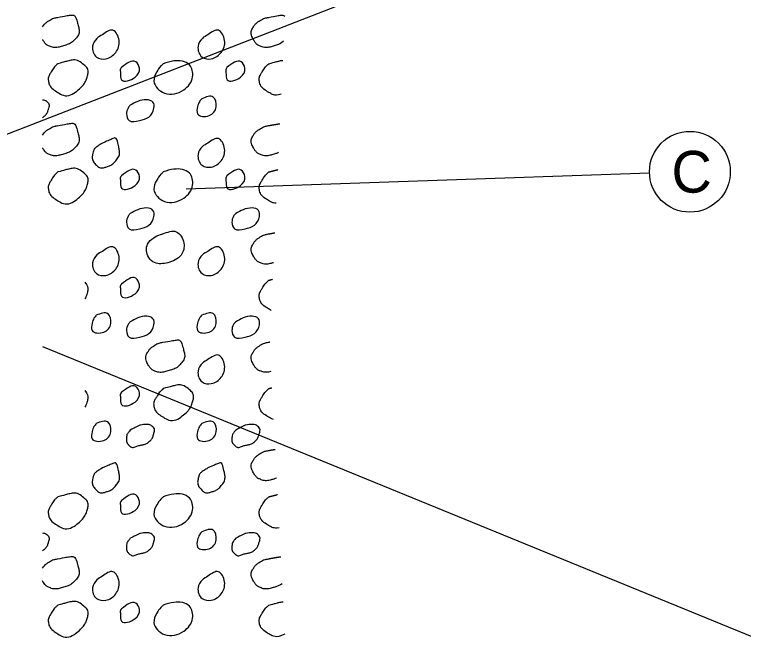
# Model space of a CAD drawing. Extents: x -1270 to 3371, y -118 to 220.
# Drawn here: x 148.55 to 172.98, y 141.14 to 162.09 of the extents above; entities that cross this region are included whole.
import ezdxf

# ---------------------------------------------------------------- set-up
doc = ezdxf.new("R2010")
doc.units = 0
for name, color, linetype in [('GE_P_Alignment', 7, 'Continuous'), ('GE_P_Alignment_100_Bearings', 7, 'Continuous'), ('TX_P_1', 7, 'Continuous')]:
    doc.layers.add(name, color=color, linetype=linetype)

msp = doc.modelspace()

# ---------------------------------------------------------------- linework, layer by layer
at = {"layer": 'GE_P_Alignment'}
msp.add_line((169.835, 156.773), (154.299, 156.237), dxfattribs=at)
at = {"layer": 'GE_P_Alignment_100_Bearings'}
for points, degree in [([(149.976, 161.994), (150.127, 162.02), (150.279, 162.049), (150.43, 162.07), (150.581, 162.091), (150.652, 161.832), (150.689, 161.69), (150.724, 161.561), (150.702, 161.403), (150.593, 161.283), (150.46, 161.136), (150.311, 161.079), (150.147, 161.031), (150.006, 160.989), (149.848, 160.974), (149.707, 161.033), (149.622, 161.069), (149.56, 161.131), (149.508, 161.211), (149.499, 161.225), (149.491, 161.239), (149.483, 161.254)], 3), ([(157.048, 161.994), (157.199, 162.02), (157.351, 162.049), (157.502, 162.07), (157.543, 162.075), (157.577, 162.061), (157.607, 162.034)], 3), ([(149.483, 161.676), (149.532, 161.752), (149.596, 161.819), (149.676, 161.87), (149.75, 161.917), (149.82, 161.961), (149.902, 161.978), (149.929, 161.984), (149.957, 161.99), (149.984, 161.996)], 3), ([(157.568, 161.193), (157.461, 161.109), (157.344, 161.068), (157.219, 161.031), (157.077, 160.989), (156.919, 160.974), (156.779, 161.033), (156.693, 161.069), (156.631, 161.131), (156.579, 161.211), (156.493, 161.345), (156.467, 161.53), (156.543, 161.656), (156.593, 161.74), (156.661, 161.814), (156.748, 161.87), (156.821, 161.917), (156.892, 161.961), (156.974, 161.978), (157.001, 161.984), (157.029, 161.99), (157.056, 161.996)], 3), ([(149.997, 160.442), (150.115, 160.474), (150.234, 160.505), (150.353, 160.536), (150.526, 160.58), (150.7, 160.549), (150.874, 160.404), (151.008, 160.292), (151.017, 160.125), (150.981, 160.001), (150.936, 159.845), (150.837, 159.696), (150.685, 159.566), (150.495, 159.404), (150.231, 159.34), (150.037, 159.456), (149.879, 159.549), (149.713, 159.689), (149.683, 159.854), (149.664, 159.957), (149.717, 160.076), (149.778, 160.172), (149.821, 160.241), (149.859, 160.31), (149.916, 160.365), (149.943, 160.391), (149.97, 160.417), (149.997, 160.442)], 3), ([(157.069, 160.442), (157.187, 160.474), (157.306, 160.505), (157.424, 160.536), (157.462, 160.545), (157.5, 160.552), (157.538, 160.554)], 3), ([(157.486, 159.419), (157.355, 159.382), (157.22, 159.389), (157.109, 159.456), (156.951, 159.549), (156.785, 159.689), (156.754, 159.854), (156.735, 159.957), (156.789, 160.076), (156.849, 160.172), (156.893, 160.241), (156.931, 160.31), (156.988, 160.365), (157.015, 160.391), (157.042, 160.417), (157.069, 160.442)], 3), ([(149.483, 159.234), (149.542, 159.229), (149.598, 159.207), (149.651, 159.154), (149.712, 159.094), (149.703, 159.014), (149.685, 158.951), (149.656, 158.846), (149.617, 158.739), (149.514, 158.654), (149.504, 158.646), (149.494, 158.638), (149.483, 158.631)], 3), ([(149.976, 158.363), (150.127, 158.389), (150.279, 158.418), (150.43, 158.439), (150.581, 158.46), (150.652, 158.201), (150.689, 158.059), (150.724, 157.93), (150.702, 157.773), (150.593, 157.653), (150.46, 157.505), (150.311, 157.448), (150.147, 157.4), (150.006, 157.359), (149.848, 157.343), (149.707, 157.403), (149.622, 157.439), (149.56, 157.501), (149.508, 157.581), (149.499, 157.595), (149.491, 157.609), (149.483, 157.623)], 3), ([(149.483, 158.046), (149.532, 158.121), (149.596, 158.188), (149.676, 158.239), (149.75, 158.286), (149.82, 158.33), (149.902, 158.348), (149.929, 158.353), (149.957, 158.359), (149.984, 158.365)], 3), ([(157.395, 157.462), (157.338, 157.437), (157.28, 157.418), (157.219, 157.4), (157.077, 157.359), (156.919, 157.343), (156.779, 157.403), (156.693, 157.439), (156.631, 157.501), (156.579, 157.581), (156.493, 157.715), (156.467, 157.899), (156.543, 158.026), (156.593, 158.11), (156.661, 158.184), (156.748, 158.239), (156.821, 158.286), (156.892, 158.33), (156.974, 158.348), (157.001, 158.353), (157.029, 158.359), (157.056, 158.365)], 3), ([(157.048, 158.363), (157.178, 158.386), (157.309, 158.41), (157.44, 158.43)], 2), ([(151.492, 157.781), (151.609, 157.831), (151.726, 157.881), (151.844, 157.932), (151.965, 157.984), (152.024, 157.717), (152.051, 157.593), (152.079, 157.462), (152.045, 157.315), (151.939, 157.188), (151.84, 157.069), (151.726, 157.012), (151.606, 156.976), (151.51, 156.947), (151.389, 156.942), (151.295, 157.035), (151.182, 157.148), (151.139, 157.28), (151.162, 157.394), (151.18, 157.485), (151.223, 157.605), (151.308, 157.662), (151.369, 157.703), (151.431, 157.741), (151.492, 157.781)], 3), ([(149.997, 156.812), (150.115, 156.843), (150.234, 156.874), (150.353, 156.905), (150.526, 156.95), (150.7, 156.918), (150.874, 156.773), (151.008, 156.661), (151.017, 156.495), (150.981, 156.371), (150.936, 156.214), (150.837, 156.066), (150.685, 155.936), (150.495, 155.774), (150.231, 155.71), (150.037, 155.825), (149.879, 155.918), (149.713, 156.058), (149.683, 156.223), (149.664, 156.326), (149.717, 156.446), (149.778, 156.542), (149.821, 156.61), (149.859, 156.679), (149.916, 156.734), (149.943, 156.76), (149.97, 156.786), (149.997, 156.812)], 3), ([(157.069, 156.812), (157.168, 156.838), (157.268, 156.865), (157.368, 156.891)], 2), ([(157.316, 155.767), (157.243, 155.769), (157.172, 155.788), (157.109, 155.825), (156.951, 155.918), (156.785, 156.058), (156.754, 156.223), (156.735, 156.326), (156.789, 156.446), (156.849, 156.542), (156.893, 156.61), (156.931, 156.679), (156.988, 156.734), (157.015, 156.76), (157.042, 156.786), (157.069, 156.812)], 3), ([(157.224, 153.771), (157.222, 153.771), (157.22, 153.77), (157.219, 153.77), (157.077, 153.728), (156.919, 153.713), (156.779, 153.772), (156.693, 153.808), (156.631, 153.87), (156.579, 153.95), (156.493, 154.084), (156.467, 154.269), (156.543, 154.395), (156.593, 154.479), (156.661, 154.553), (156.748, 154.609), (156.821, 154.656), (156.892, 154.7), (156.974, 154.717), (157.001, 154.723), (157.029, 154.729), (157.056, 154.735)], 3), ([(157.048, 154.733), (157.122, 154.746), (157.196, 154.759), (157.27, 154.772)], 2), ([(150.9, 153.119), (151.009, 153.008), (151.014, 152.856), (150.981, 152.74), (150.963, 152.677), (150.936, 152.615), (150.9, 152.555)], 3), ([(157.149, 152.173), (157.136, 152.18), (157.122, 152.187), (157.109, 152.195), (156.951, 152.288), (156.785, 152.428), (156.754, 152.593), (156.735, 152.696), (156.789, 152.815), (156.849, 152.911), (156.893, 152.98), (156.931, 153.049), (156.988, 153.104), (157.015, 153.13), (157.042, 153.156), (157.069, 153.181)], 3), ([(157.069, 153.181), (157.112, 153.193), (157.155, 153.204), (157.198, 153.215)], 2), ([(153.512, 151.102), (153.663, 151.128), (153.815, 151.157), (153.966, 151.178), (154.117, 151.199), (154.187, 150.94), (154.225, 150.798), (154.26, 150.669), (154.237, 150.512), (154.129, 150.392), (153.995, 150.244), (153.847, 150.187), (153.683, 150.139), (153.542, 150.098), (153.383, 150.082), (153.243, 150.142), (153.157, 150.178), (153.095, 150.24), (153.044, 150.32), (152.957, 150.454), (152.931, 150.638), (153.007, 150.765), (153.057, 150.849), (153.125, 150.923), (153.212, 150.978), (153.286, 151.025), (153.356, 151.069), (153.438, 151.087), (153.465, 151.092), (153.493, 151.098), (153.52, 151.104)], 3), ([(157.139, 150.119), (157.019, 150.095), (156.893, 150.093), (156.779, 150.142), (156.693, 150.178), (156.631, 150.24), (156.579, 150.32), (156.493, 150.454), (156.467, 150.638), (156.543, 150.765), (156.593, 150.849), (156.661, 150.923), (156.748, 150.978), (156.821, 151.025), (156.892, 151.069), (156.974, 151.087), (157.001, 151.092), (157.029, 151.098), (157.056, 151.104)], 3), ([(157.048, 151.102), (157.065, 151.105), (157.083, 151.108), (157.1, 151.112)], 2), ([(153.533, 149.551), (153.651, 149.582), (153.77, 149.613), (153.889, 149.644), (154.062, 149.689), (154.236, 149.657), (154.409, 149.512), (154.544, 149.4), (154.553, 149.234), (154.517, 149.11), (154.472, 148.953), (154.373, 148.805), (154.221, 148.675), (154.031, 148.513), (153.767, 148.449), (153.573, 148.564), (153.415, 148.657), (153.249, 148.797), (153.219, 148.962), (153.2, 149.065), (153.253, 149.185), (153.314, 149.281), (153.357, 149.349), (153.395, 149.418), (153.452, 149.473), (153.479, 149.499), (153.506, 149.525), (153.533, 149.551)], 3), ([(157.069, 149.551), (157.102, 149.56), (157.135, 149.568), (157.168, 149.577)], 2), ([(150.9, 149.488), (151.009, 149.377), (151.014, 149.225), (150.981, 149.11), (150.963, 149.046), (150.936, 148.984), (150.9, 148.924)], 3), ([(157.225, 148.518), (157.184, 148.527), (157.145, 148.542), (157.109, 148.564), (156.951, 148.657), (156.785, 148.797), (156.754, 148.962), (156.735, 149.065), (156.789, 149.185), (156.849, 149.281), (156.893, 149.349), (156.931, 149.418), (156.988, 149.473), (157.015, 149.499), (157.042, 149.525), (157.069, 149.551)], 3), ([(152.425, 148.161), (152.509, 148.203), (152.592, 148.245), (152.675, 148.286), (152.767, 148.332), (152.876, 148.341), (152.976, 148.344), (153.05, 148.346), (153.121, 148.329), (153.187, 148.263), (153.248, 148.203), (153.239, 148.123), (153.221, 148.059), (153.192, 147.954), (153.152, 147.848), (153.05, 147.763), (152.95, 147.68), (152.844, 147.668), (152.737, 147.643), (152.624, 147.617), (152.495, 147.55), (152.385, 147.649), (152.313, 147.714), (152.297, 147.79), (152.299, 147.864), (152.301, 147.931), (152.309, 148.009), (152.351, 148.064), (152.376, 148.097), (152.4, 148.129), (152.425, 148.161)], 3), ([(155.961, 148.161), (156.044, 148.203), (156.128, 148.245), (156.211, 148.286), (156.303, 148.332), (156.412, 148.341), (156.512, 148.344), (156.585, 148.346), (156.656, 148.329), (156.723, 148.263), (156.783, 148.203), (156.775, 148.123), (156.757, 148.059), (156.727, 147.954), (156.688, 147.848), (156.586, 147.763), (156.486, 147.68), (156.38, 147.668), (156.273, 147.643), (156.16, 147.617), (156.031, 147.55), (155.921, 147.649), (155.848, 147.714), (155.833, 147.79), (155.835, 147.864), (155.837, 147.931), (155.845, 148.009), (155.887, 148.064), (155.912, 148.097), (155.936, 148.129), (155.961, 148.161)], 3), ([(157.331, 146.545), (157.294, 146.532), (157.257, 146.52), (157.219, 146.509), (157.077, 146.467), (156.919, 146.452), (156.779, 146.511), (156.693, 146.547), (156.631, 146.609), (156.579, 146.689), (156.493, 146.823), (156.467, 147.008), (156.543, 147.134), (156.593, 147.218), (156.661, 147.292), (156.748, 147.348), (156.821, 147.395), (156.892, 147.439), (156.974, 147.456), (157.001, 147.462), (157.029, 147.468), (157.056, 147.474)], 3), ([(157.048, 147.472), (157.125, 147.485), (157.202, 147.499), (157.279, 147.512)], 2), ([(151.492, 146.889), (151.609, 146.94), (151.726, 146.99), (151.844, 147.04), (151.965, 147.092), (152.024, 146.826), (152.051, 146.702), (152.079, 146.571), (152.045, 146.424), (151.939, 146.297), (151.84, 146.177), (151.726, 146.121), (151.606, 146.084), (151.51, 146.055), (151.389, 146.051), (151.295, 146.144), (151.182, 146.256), (151.139, 146.388), (151.162, 146.503), (151.18, 146.594), (151.223, 146.714), (151.308, 146.77), (151.369, 146.811), (151.431, 146.85), (151.492, 146.889)], 3), ([(155.028, 146.889), (155.145, 146.94), (155.262, 146.99), (155.379, 147.04), (155.501, 147.092), (155.56, 146.826), (155.587, 146.702), (155.615, 146.571), (155.581, 146.424), (155.475, 146.297), (155.376, 146.177), (155.262, 146.121), (155.142, 146.084), (155.046, 146.055), (154.925, 146.051), (154.831, 146.144), (154.717, 146.256), (154.675, 146.388), (154.698, 146.503), (154.716, 146.594), (154.758, 146.714), (154.844, 146.77), (154.905, 146.811), (154.967, 146.85), (155.028, 146.889)], 3), ([(149.997, 145.92), (150.115, 145.952), (150.234, 145.983), (150.353, 146.014), (150.526, 146.059), (150.7, 146.027), (150.874, 145.882), (151.008, 145.77), (151.017, 145.604), (150.981, 145.479), (150.936, 145.323), (150.837, 145.174), (150.685, 145.044), (150.495, 144.882), (150.231, 144.819), (150.037, 144.934), (149.879, 145.027), (149.713, 145.167), (149.683, 145.332), (149.664, 145.435), (149.717, 145.555), (149.778, 145.65), (149.821, 145.719), (149.859, 145.788), (149.916, 145.843), (149.943, 145.869), (149.97, 145.895), (149.997, 145.92)], 3), ([(157.42, 144.882), (157.311, 144.864), (157.202, 144.878), (157.109, 144.934), (156.951, 145.027), (156.785, 145.167), (156.754, 145.332), (156.735, 145.435), (156.789, 145.555), (156.849, 145.65), (156.893, 145.719), (156.931, 145.788), (156.988, 145.843), (157.015, 145.869), (157.042, 145.895), (157.069, 145.92)], 3), ([(157.069, 145.92), (157.166, 145.946), (157.263, 145.972), (157.36, 145.997)], 2), ([(149.483, 144.712), (149.542, 144.707), (149.598, 144.685), (149.651, 144.632), (149.712, 144.572), (149.703, 144.492), (149.685, 144.429), (149.656, 144.324), (149.617, 144.217), (149.514, 144.132), (149.504, 144.124), (149.494, 144.116), (149.483, 144.109)], 3), ([(152.425, 144.531), (152.509, 144.573), (152.592, 144.614), (152.675, 144.656), (152.767, 144.701), (152.876, 144.71), (152.976, 144.713), (153.05, 144.715), (153.121, 144.698), (153.187, 144.632), (153.248, 144.572), (153.239, 144.492), (153.221, 144.429), (153.192, 144.324), (153.152, 144.217), (153.05, 144.132), (152.95, 144.049), (152.844, 144.037), (152.737, 144.012), (152.624, 143.986), (152.495, 143.919), (152.385, 144.018), (152.313, 144.083), (152.297, 144.16), (152.299, 144.234), (152.301, 144.3), (152.309, 144.379), (152.351, 144.434), (152.376, 144.467), (152.4, 144.499), (152.425, 144.531)], 3), ([(155.961, 144.531), (156.044, 144.573), (156.128, 144.614), (156.211, 144.656), (156.303, 144.701), (156.412, 144.71), (156.512, 144.713), (156.585, 144.715), (156.656, 144.698), (156.723, 144.632), (156.783, 144.572), (156.775, 144.492), (156.757, 144.429), (156.727, 144.324), (156.688, 144.217), (156.586, 144.132), (156.486, 144.049), (156.38, 144.037), (156.273, 144.012), (156.16, 143.986), (156.031, 143.919), (155.921, 144.018), (155.848, 144.083), (155.833, 144.16), (155.835, 144.234), (155.837, 144.3), (155.845, 144.379), (155.887, 144.434), (155.912, 144.467), (155.936, 144.499), (155.961, 144.531)], 3), ([(149.976, 143.841), (150.127, 143.867), (150.279, 143.896), (150.43, 143.917), (150.581, 143.938), (150.652, 143.679), (150.689, 143.537), (150.724, 143.408), (150.702, 143.251), (150.593, 143.131), (150.46, 142.983), (150.311, 142.927), (150.147, 142.878), (150.006, 142.837), (149.848, 142.821), (149.707, 142.881), (149.622, 142.917), (149.56, 142.979), (149.508, 143.059), (149.499, 143.073), (149.491, 143.087), (149.483, 143.101)], 3), ([(149.483, 143.524), (149.532, 143.599), (149.596, 143.666), (149.676, 143.717), (149.75, 143.764), (149.82, 143.808), (149.902, 143.826), (149.929, 143.831), (149.957, 143.837), (149.984, 143.843)], 3), ([(157.521, 143.007), (157.427, 142.945), (157.326, 142.91), (157.219, 142.878), (157.077, 142.837), (156.919, 142.821), (156.779, 142.881), (156.693, 142.917), (156.631, 142.979), (156.579, 143.059), (156.493, 143.193), (156.467, 143.378), (156.543, 143.504), (156.593, 143.588), (156.661, 143.662), (156.748, 143.717), (156.821, 143.764), (156.892, 143.808), (156.974, 143.826), (157.001, 143.831), (157.029, 143.837), (157.056, 143.843)], 3), ([(157.048, 143.841), (157.189, 143.866), (157.331, 143.892), (157.472, 143.913)], 2), ([(149.997, 142.29), (150.115, 142.321), (150.234, 142.352), (150.353, 142.383), (150.526, 142.428), (150.7, 142.396), (150.874, 142.251), (151.008, 142.139), (151.017, 141.973), (150.981, 141.849), (150.936, 141.692), (150.837, 141.544), (150.685, 141.414), (150.495, 141.252), (150.231, 141.188), (150.037, 141.303), (149.879, 141.396), (149.713, 141.536), (149.683, 141.701), (149.664, 141.804), (149.717, 141.924), (149.778, 142.02), (149.821, 142.088), (149.859, 142.157), (149.916, 142.212), (149.943, 142.238), (149.97, 142.264), (149.997, 142.29)], 3), ([(157.612, 141.316), (157.446, 141.232), (157.257, 141.215), (157.109, 141.303), (156.951, 141.396), (156.785, 141.536), (156.754, 141.701), (156.735, 141.804), (156.789, 141.924), (156.849, 142.02), (156.893, 142.088), (156.931, 142.157), (156.988, 142.212), (157.015, 142.238), (157.042, 142.264), (157.069, 142.29)], 3), ([(157.069, 142.29), (157.187, 142.321), (157.306, 142.352), (157.424, 142.383), (157.467, 142.394), (157.51, 142.401), (157.553, 142.402)], 3)]:
    msp.add_open_spline(points, degree=degree, dxfattribs=at)
for points in [[(151.492, 161.411), (151.844, 161.562), (152.051, 161.224), (151.939, 160.819), (151.606, 160.606), (151.295, 160.666), (151.162, 161.025), (151.308, 161.292), (151.492, 161.411)], [(155.028, 161.411), (155.379, 161.562), (155.587, 161.224), (155.475, 160.819), (155.142, 160.606), (154.831, 160.666), (154.698, 161.025), (154.844, 161.292), (155.028, 161.411)], [(152.134, 160.316), (152.609, 160.509), (152.734, 160.291), (152.585, 159.988), (152.135, 159.904), (152.096, 160.144), (152.1, 160.265), (152.134, 160.316)], [(153.533, 160.442), (153.889, 160.536), (154.409, 160.404), (154.517, 160.001), (154.221, 159.566), (153.573, 159.456), (153.219, 159.854), (153.314, 160.172), (153.452, 160.365), (153.533, 160.442)], [(155.669, 160.316), (156.144, 160.509), (156.27, 160.291), (156.121, 159.988), (155.671, 159.904), (155.632, 160.144), (155.636, 160.265), (155.669, 160.316)], [(154.824, 159.269), (155.205, 159.325), (155.309, 158.997), (155.069, 158.703), (154.683, 158.759), (154.685, 159.005), (154.744, 159.168), (154.824, 159.269)], [(152.425, 159.053), (152.675, 159.178), (152.976, 159.235), (153.187, 159.154), (153.221, 158.951), (153.05, 158.654), (152.737, 158.534), (152.385, 158.54), (152.299, 158.756), (152.351, 158.956), (152.425, 159.053)], [(155.028, 157.781), (155.379, 157.932), (155.587, 157.593), (155.475, 157.188), (155.142, 156.976), (154.831, 157.035), (154.698, 157.394), (154.844, 157.662), (155.028, 157.781)], [(152.134, 156.686), (152.609, 156.878), (152.734, 156.66), (152.585, 156.358), (152.135, 156.273), (152.096, 156.513), (152.1, 156.634), (152.134, 156.686)], [(153.533, 156.812), (153.889, 156.905), (154.409, 156.773), (154.517, 156.371), (154.221, 155.936), (153.573, 155.825), (153.219, 156.223), (153.314, 156.542), (153.452, 156.734), (153.533, 156.812)], [(155.669, 156.686), (156.144, 156.878), (156.27, 156.66), (156.121, 156.358), (155.671, 156.273), (155.632, 156.513), (155.636, 156.634), (155.669, 156.686)], [(152.425, 155.422), (152.675, 155.547), (152.976, 155.605), (153.187, 155.524), (153.221, 155.32), (153.05, 155.024), (152.737, 154.904), (152.385, 154.91), (152.299, 155.125), (152.351, 155.325), (152.425, 155.422)], [(155.961, 155.422), (156.211, 155.547), (156.512, 155.605), (156.723, 155.524), (156.757, 155.32), (156.586, 155.024), (156.273, 154.904), (155.921, 154.91), (155.835, 155.125), (155.887, 155.325), (155.961, 155.422)], [(153.512, 154.733), (153.966, 154.809), (154.225, 154.429), (154.129, 154.022), (153.683, 153.77), (153.243, 153.772), (153.044, 153.95), (153.007, 154.395), (153.212, 154.609), (153.438, 154.717), (153.52, 154.735)], [(151.492, 154.15), (151.844, 154.301), (152.051, 153.963), (151.939, 153.558), (151.606, 153.345), (151.295, 153.405), (151.162, 153.764), (151.308, 154.031), (151.492, 154.15)], [(155.028, 154.15), (155.379, 154.301), (155.587, 153.963), (155.475, 153.558), (155.142, 153.345), (154.831, 153.405), (154.698, 153.764), (154.844, 154.031), (155.028, 154.15)], [(152.134, 153.055), (152.609, 153.248), (152.734, 153.03), (152.585, 152.727), (152.135, 152.643), (152.096, 152.883), (152.1, 153.004), (152.134, 153.055)], [(151.288, 152.008), (151.669, 152.064), (151.774, 151.736), (151.534, 151.442), (151.147, 151.498), (151.149, 151.744), (151.208, 151.907), (151.288, 152.008)], [(154.824, 152.008), (155.205, 152.064), (155.309, 151.736), (155.069, 151.442), (154.683, 151.498), (154.685, 151.744), (154.744, 151.907), (154.824, 152.008)], [(152.425, 151.792), (152.675, 151.917), (152.976, 151.974), (153.187, 151.893), (153.221, 151.69), (153.05, 151.393), (152.737, 151.273), (152.385, 151.279), (152.299, 151.495), (152.351, 151.695), (152.425, 151.792)], [(155.961, 151.792), (156.211, 151.917), (156.512, 151.974), (156.723, 151.893), (156.757, 151.69), (156.586, 151.393), (156.273, 151.273), (155.921, 151.279), (155.835, 151.495), (155.887, 151.695), (155.961, 151.792)], [(155.028, 150.52), (155.379, 150.671), (155.587, 150.332), (155.475, 149.927), (155.142, 149.715), (154.831, 149.774), (154.698, 150.133), (154.844, 150.401), (155.028, 150.52)], [(152.134, 149.425), (152.609, 149.617), (152.734, 149.399), (152.585, 149.097), (152.135, 149.012), (152.096, 149.252), (152.1, 149.373), (152.134, 149.425)], [(151.288, 148.378), (151.669, 148.434), (151.774, 148.105), (151.534, 147.811), (151.147, 147.868), (151.149, 148.114), (151.208, 148.277), (151.288, 148.378)], [(154.824, 148.378), (155.205, 148.434), (155.309, 148.105), (155.069, 147.811), (154.683, 147.868), (154.685, 148.114), (154.744, 148.277), (154.824, 148.378)], [(152.134, 145.794), (152.609, 145.987), (152.734, 145.769), (152.585, 145.466), (152.135, 145.382), (152.096, 145.622), (152.1, 145.743), (152.134, 145.794)], [(153.533, 145.92), (153.889, 146.014), (154.409, 145.882), (154.517, 145.479), (154.221, 145.044), (153.573, 144.934), (153.219, 145.332), (153.314, 145.65), (153.452, 145.843), (153.533, 145.92)], [(154.824, 144.747), (155.205, 144.803), (155.309, 144.475), (155.069, 144.181), (154.683, 144.237), (154.685, 144.483), (154.744, 144.646), (154.824, 144.747)], [(151.492, 143.259), (151.844, 143.41), (152.051, 143.071), (151.939, 142.666), (151.606, 142.454), (151.295, 142.513), (151.162, 142.872), (151.308, 143.14), (151.492, 143.259)], [(155.028, 143.259), (155.379, 143.41), (155.587, 143.071), (155.475, 142.666), (155.142, 142.454), (154.831, 142.513), (154.698, 142.872), (154.844, 143.14), (155.028, 143.259)], [(152.134, 142.164), (152.609, 142.356), (152.734, 142.138), (152.585, 141.836), (152.135, 141.751), (152.096, 141.991), (152.1, 142.112), (152.134, 142.164)], [(153.533, 142.29), (153.889, 142.383), (154.409, 142.251), (154.517, 141.849), (154.221, 141.414), (153.573, 141.303), (153.219, 141.701), (153.314, 142.02), (153.452, 142.212), (153.533, 142.29)]]:
    msp.add_spline(points, degree=3, dxfattribs=at)
at = {"layer": 'TX_P_1'}
for p, q in [((129.983, 150.963), (172.267, 167.403)), ((149.483, 150.963), (173.509, 141.14))]:
    msp.add_line(p, q, dxfattribs=at)
msp.add_circle((171.189, 156.819), 1.355, dxfattribs=at)

# ---------------------------------------------------------------- texts
msp.add_text('C', height=1.4, dxfattribs=at).set_placement((170.572, 156.119))

doc.saveas('drawing.dxf')
